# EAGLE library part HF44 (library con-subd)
SUB-D
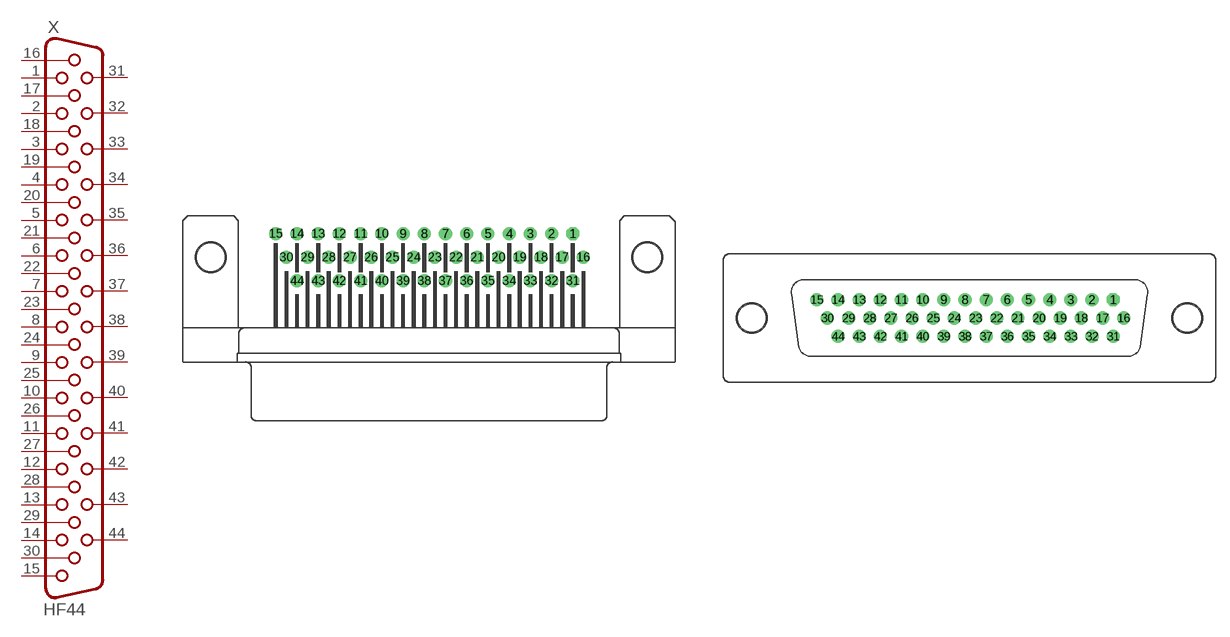
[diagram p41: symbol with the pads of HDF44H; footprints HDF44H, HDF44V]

Designator prefix X

## HF44H (OC_FARNELL: unknown; OC_NEWARK: unknown)  [HDF44H]
1  1  pas
2  2  pas
3  3  pas
4  4  pas
5  5  pas
6  6  pas
7  7  pas
8  8  pas
9  9  pas
10  10  pas
11  11  pas
12  12  pas
13  13  pas
14  14  pas
15  15  pas
16  16  pas
17  17  pas
18  18  pas
19  19  pas
20  20  pas
21  21  pas
22  22  pas
23  23  pas
24  24  pas
25  25  pas
26  26  pas
27  27  pas
28  28  pas
29  29  pas
30  30  pas
31  31  pas
32  32  pas
33  33  pas
34  34  pas
35  35  pas
36  36  pas
37  37  pas
38  38  pas
39  39  pas
40  40  pas
41  41  pas
42  42  pas
43  43  pas
44  44  pas

## HF44V (OC_FARNELL: unknown; OC_NEWARK: unknown)  [HDF44V]
Pads as for HDF44H

## HF44HN (OC_FARNELL: unknown; OC_NEWARK: unknown)  [HDF44HN]
Pads as for HDF44H

## Footprint HDF44H (pad centres in mm)
SUB-D
drill 0.9 octagon: 1 15.497,2.54
drill 0.9 round: 2 13.211,2.54; 3 10.925,2.54; 4 8.639,2.54; 5 6.353,2.54; 6 4.067,2.54; 7 1.781,2.54; 8 -0.505,2.54; 9 -2.791,2.54; 10 -5.077,2.54; 11 -7.363,2.54; 12 -9.649,2.54; 13 -11.935,2.54; 14 -14.221,2.54; 15 -16.507,2.54; 16 16.64,0; 17 14.354,0; 18 12.068,0; 19 9.782,0; 20 7.496,0; 21 5.21,0; 22 2.924,0; 23 0.638,0; 24 -1.648,0; 25 -3.934,0; 26 -6.22,0; 27 -8.506,0; 28 -10.792,0; 29 -13.078,0; 30 -15.364,0; 31 15.497,-2.54; 32 13.211,-2.54; 33 10.925,-2.54; 34 8.639,-2.54; 35 6.353,-2.54; 36 4.067,-2.54; 37 1.781,-2.54; 38 -0.505,-2.54; 39 -2.791,-2.54; 40 -5.077,-2.54; 41 -7.363,-2.54; 42 -9.649,-2.54; 43 -11.935,-2.54; 44 -14.221,-2.54
hole 3 at -23.52,0
hole 3 at 23.52,0

## Footprint HDF44V (pad centres in mm)
SUB-D
drill 0.9 octagon: 1 15.516,1.98
drill 0.9 round: 2 13.23,1.98; 3 10.944,1.98; 4 8.658,1.98; 5 6.372,1.98; 6 4.086,1.98; 7 1.8,1.98; 8 -0.486,1.98; 9 -2.772,1.98; 10 -5.058,1.98; 11 -7.344,1.98; 12 -9.63,1.98; 13 -11.916,1.98; 14 -14.202,1.98; 15 -16.488,1.98; 16 16.659,0; 17 14.373,0; 18 12.087,0; 19 9.801,0; 20 7.515,0; 21 5.229,0; 22 2.943,0; 23 0.657,0; 24 -1.629,0; 25 -3.915,0; 26 -6.201,0; 27 -8.487,0; 28 -10.773,0; 29 -13.059,0; 30 -15.345,0; 31 15.516,-1.98; 32 13.23,-1.98; 33 10.944,-1.98; 34 8.658,-1.98; 35 6.372,-1.98; 36 4.086,-1.98; 37 1.8,-1.98; 38 -0.486,-1.98; 39 -2.772,-1.98; 40 -5.058,-1.98; 41 -7.344,-1.98; 42 -9.63,-1.98; 43 -11.916,-1.98; 44 -14.202,-1.98
hole 3 at -23.52,0
hole 3 at 23.52,0

## Footprint HDF44HN (pad centres in mm)
SUB-D
drill 0.813 octagon: 1 -14.732,-3.81; 2 -12.446,-3.81; 3 -10.16,-3.81; 4 -7.874,-3.81; 5 -5.588,-3.81; 6 -3.302,-3.81; 7 -1.016,-3.81; 8 1.27,-3.81; 9 3.556,-3.81; 10 5.842,-3.81; 11 8.128,-3.81; 12 10.414,-3.81; 13 12.7,-3.81; 14 14.986,-3.81; 15 17.272,-3.81; 16 -15.875,-1.27; 17 -13.589,-1.27; 18 -11.303,-1.27; 19 -9.017,-1.27; 20 -6.731,-1.27; 21 -4.445,-1.27; 22 -2.159,-1.27; 23 0.127,-1.27; 24 2.413,-1.27; 25 4.699,-1.27; 26 6.985,-1.27; 27 9.271,-1.27; 28 11.557,-1.27; 29 13.843,-1.27; 30 16.129,-1.27; 31 -14.732,1.27; 32 -12.446,1.27; 33 -10.16,1.27; 34 -7.874,1.27; 35 -5.588,1.27; 36 -3.302,1.27; 37 -1.016,1.27; 38 1.27,1.27; 39 3.556,1.27; 40 5.842,1.27; 41 8.128,1.27; 42 10.414,1.27; 43 12.7,1.27; 44 14.986,1.27
drill 3.302 pad 5.08 round: G1 -22.936,-1.27; G2 24.166,-1.27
